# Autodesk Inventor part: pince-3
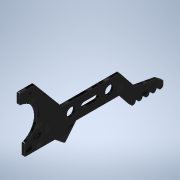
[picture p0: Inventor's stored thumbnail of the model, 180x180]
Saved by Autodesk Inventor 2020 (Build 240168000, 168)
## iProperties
Created: 2021-10
Part Number: pince-3
Material: Générique
Document SubType Name: Modeling
Designer: bruno
Density: 1 g/cm^3
Appearance: Noir
Author: bruno
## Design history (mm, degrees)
sketch "Esquisse1"
  geometry: L1 (-1.405, -17.044)-(-13.576, -17.044); L2 (-8.905, -22.629)-(-8.905, -39.629); L3 (-8.905, -39.629)-(-1.405, -39.629); L4 (-1.405, -39.629)-(-1.405, -17.044); L5 (11.235, -0.938)-(11.235, -6.438); L6 (11.235, -6.438)-(-1.405, -17.044); L7 (-14.367, -44.006)-(-8.905, -39.629); L8 (-11.241, -14.35)-(-14.055, -17.862); L9 (-13.977, -18.565)-(-8.905, -22.629); L10 (-1.405, -39.629)-(-8.919, -45.65); L11 (-8.919, -45.65)-(-10.585, -54.305); L12 (-10.585, -54.305)-(-12.388, -56.703); L13 (-12.388, -56.703)-(-13.801, -56.703); L14 (0, 7)-(0, -8.75); L15 (-14.367, -44.006)-(-14.518, -44.127); L16 (-14.367, -18.252)-(-14.367, -44.027); L17 (-14.387, -56.513)-(-14.387, -56.734); L18 (-13.797, -45.901)-(-13.797, -46.603); L19 (11.235, 3.954)-(11.064, 3.896); L20 (11.877, 1.042)-(11.627, 0.987); L21 (11.235, 0.579)-(11.235, 0.499); L22 (9.44, 6.119)-(9.48, 6.05); L23 (9.765, 6.841)-(9.576, 6.669); L24 (7.753, 9.042)-(7.634, 8.906); L25 (5.116, 10.019)-(5.186, 9.979); L26 (5.036, 10.807)-(4.959, 10.563); L27 (2.193, 11.707)-(2.158, 11.53); L28 (-0.579, 11.235)-(-0.499, 11.235); L29 (-1.042, 11.877)-(-0.987, 11.627); L30 (-3.954, 11.235)-(-3.896, 11.064); L31 (-6.119, 9.44)-(-6.05, 9.48); L32 (-6.841, 9.765)-(-6.669, 9.576); L33 (-9.042, 7.753)-(-8.906, 7.634); L34 (-10.019, 5.116)-(-9.979, 5.186); L35 (-10.807, 5.036)-(-10.563, 4.959); L36 (-11.707, 2.193)-(-11.53, 2.158); L37 (-11.235, -0.579)-(-11.235, -0.499); L38 (-11.877, -1.042)-(-11.627, -0.987); L39 (-11.235, -3.954)-(-11.064, -3.896); L40 (10.427, -4.223)-(10.393, -4.296); L41 (11.853, -1.165)-(11.674, -1.145); L42 (11.205, -4.075)-(10.955, -4.019); L43 (-4.155, -25.629)-(-4.155, -30.629); L44 (-6.155, -25.629)-(-6.155, -30.629); L45 (7.691, -0.438)-(10.735, -0.438); L46 (11.235, -0.438)-(11.235, -6.438); L47 (-7.205, -2.35)-(-10.741, -2.35); L48 (7.235, -6.438)-(7.235, -5.633); L49 (7.235, -1.56)-(7.235, -0.438); L50 (11.235, -6.438)-(9.221, -6.438); L51 (7.971, -6.438)-(7.235, -6.438); L52 (-11.241, -0.35)-(-11.241, -0.574); L53 (-11.241, -2.85)-(-11.241, -14.35); A1 r 1 centre (-13.89, -44.906) between (-14.367, -44.027) and (-13.537, -45.841); A2 r 1 centre (-13.771, -47.603) between (-13.797, -46.603) and (-13.801, -48.603); A3 r 1 centre (-13.801, -50.303) between (-13.801, -49.303) and (-13.801, -51.303); A4 r 1 centre (-13.801, -53.003) between (-13.801, -52.003) and (-13.801, -54.003); A5 r 1 centre (-13.801, -55.703) between (-13.801, -54.703) and (-13.801, -56.703); A6 r 1.5 centre (11.718, 2.534) between (11.877, 1.042) and (11.235, 3.954); A7 r 0.5 centre (10.903, 4.369) between (10.439, 4.183) and (11.064, 3.896); A8 r 0.5 centre (11.735, 0.499) between (11.627, 0.987) and (11.235, 0.499); A9 r 0.5 centre (9.913, 6.3) between (9.576, 6.669) and (9.48, 6.05); A10 r 1.5 centre (8.881, 8.053) between (9.765, 6.841) and (7.753, 9.042); A11 r 0.5 centre (7.258, 9.235) between (6.949, 8.842) and (7.634, 8.906); A12 r 0.5 centre (5.436, 10.412) between (4.959, 10.563) and (5.186, 9.979); A13 r 1.5 centre (3.665, 11.415) between (5.036, 10.807) and (2.193, 11.707); A14 r 0.5 centre (1.668, 11.627) between (1.597, 11.132) and (2.158, 11.53); A15 r 0.5 centre (-0.499, 11.735) between (-0.987, 11.627) and (-0.499, 11.235); A16 r 1.5 centre (-2.534, 11.718) between (-1.042, 11.877) and (-3.954, 11.235); A17 r 0.5 centre (-4.369, 10.903) between (-4.183, 10.439) and (-3.896, 11.064); A18 r 0.5 centre (-6.3, 9.913) between (-6.669, 9.576) and (-6.05, 9.48); A19 r 1.5 centre (-8.053, 8.881) between (-6.841, 9.765) and (-9.042, 7.753); A20 r 0.5 centre (-9.235, 7.258) between (-8.842, 6.949) and (-8.906, 7.634); A21 r 0.5 centre (-10.412, 5.436) between (-10.563, 4.959) and (-9.979, 5.186); A22 r 1.5 centre (-11.415, 3.665) between (-10.807, 5.036) and (-11.707, 2.193); A23 r 0.5 centre (-11.627, 1.668) between (-11.132, 1.597) and (-11.53, 2.158); A24 r 0.5 centre (-11.735, -0.499) between (-11.627, -0.987) and (-11.235, -0.499); A25 r 1.5 centre (-11.718, -2.534) between (-11.877, -1.042) and (-11.235, -3.954); A26 r 0.5 centre (-10.903, -4.369) between (-10.439, -4.183) and (-11.064, -3.896); A27 r 0.5 centre (11.728, -0.648) between (11.229, -0.621) and (11.674, -1.145); A28 r 0.5 centre (10.846, -4.507) between (10.955, -4.019) and (10.393, -4.296); A29 r 1.5 centre (11.691, -2.656) between (11.205, -4.075) and (11.853, -1.165); A30 r 1 centre (-5.155, -30.629) between (-6.155, -30.629) and (-4.155, -30.629); A31 r 1 centre (-5.155, -25.629) between (-4.155, -25.629) and (-6.155, -25.629); A32 r 7.248 centre (0, 0) between (-6.74, -2.666) and (7.195, -0.878); A33 r 0.5 centre (10.735, -0.938) between (11.235, -0.938) and (10.735, -0.438); A34 r 0.5 centre (7.691, -0.938) between (7.691, -0.438) and (7.195, -0.878); A35 r 0.5 centre (-7.205, -2.85) between (-6.74, -2.666) and (-7.205, -2.35); A36 r 0.5 centre (-10.741, -2.85) between (-10.741, -2.35) and (-11.241, -2.85); A37 r 11.246 centre (0, 0) between (6.05, 9.48) and (5.186, 9.979); A38 r 11.246 centre (0, 0) between (0.499, 11.235) and (-0.499, 11.235); A39 r 11.246 centre (0, 0) between (-8.842, 6.949) and (-9.48, 6.05); A40 r 11.246 centre (0, 0) between (-9.96, 5.223) and (-9.979, 5.186); A41 r 11.246 centre (0, 0) between (-4.183, 10.439) and (-5.186, 9.979); A42 r 11.246 centre (0, 0) between (-6.014, 9.503) and (-6.05, 9.48); A43 r 11.246 centre (0, 0) between (-11.132, 1.597) and (-11.208, 0.922); A44 r 11.246 centre (0, 0) between (-11.235, 0.499) and (-11.241, -0.35); A45 r 0.5 centre (-13.664, -18.174) between (-14.055, -17.862) and (-13.977, -18.565); 15 further points; 1 other entity
  constraints: 106 end point, 99 point on circle, 45 centre point, 25 point on line, 17 tangent, 8 parallel, 7 perpendicular, 7 vertical, 6 horizontal, 3 coincident, 3 equal radius, 131 other
  dimensions: "d3" = 7 distance of point (0, 0) L14.start; "d6" = 7.5 distance of L3.end L2.end; "d9" = 16.5 distance of L5.end L1.start; "d10" = 14 distance of L52.start L8.start; "d11" = 5 distance of L8.start L16.start; "d12" = 7 distance of L2.start L16.start; "d13" = 17 distance of L2.start L2.end; "d16" = 7 distance of L7.start L2.end; "d17" = 3 distance of L11.end L12.end; "d18" = 2 distance of L17.end L12.end; "d20" = 2 diameter of A2; "d21" = 2 diameter of A1; "d22" = 2 diameter of A3; "d24" = 2 diameter of A4; "d25" = 2.7 distance of A1.centre A2.centre; "d26" = 2.7 distance of A2.centre A3.centre; "d27" = 2.7 distance of A4.centre A3.centre; "d28" = 2 diameter of A5; "d29" = 2.7 distance of A5.centre A4.centre; "d30" = 3 diameter of A6; "d31" = 0.5 radius of A7 (derived); "d32" = 0.5 radius of A8 (derived); "d35" = 180 deg dimension on A37.centre A8.centre A24.centre; "d39" = 25 deg dimension on point (0, 0) L40.start L21.start; "d44" = 2 diameter of A30; "d45" = 2 diameter of A31; "d46" = 5 distance of A30.centre A31.centre; "d47" = 3 vertical distance of L2.start A31.centre; "d52" = 3.75 distance from line of A30.centre L2; "d53" = 3.75 distance from line of L2 A31.centre; "d64" = 4 distance of L49.end L46.start; "d65" = 6 distance of L48.start L49.end; "d66" = 130 deg angle of L4 L6; "d67" = 12 distance from line of L47 L8.start; "d68" = 0.5 radius of A33; "d69" = 0.5 radius of A45 (derived)
node "Plan de construction1"
extrude "Extrusion4" join sketch "Esquisse1" distance "d70" = 1; taper "d71" = 0 deg
sketch "Esquisse2"
  geometry: C1 r 1.75 at (20.703, -5.155); C2 r 1.75 at (35.703, -5.177); 3 further points
  constraints: 2 centre point, 2 coincident
  dimensions: "d56" = 15 distance of point (20.703, -5.155) point (35.703, -5.177); "d62" = 3.5 diameter of C1; "d63" = 3.5 diameter of C2
extrude "Extrusion3" cut sketch "Esquisse2" distance "d54" = 10; taper "d55" = 0 deg
node "Solide2"
other parameters: "d5" = 22.5
